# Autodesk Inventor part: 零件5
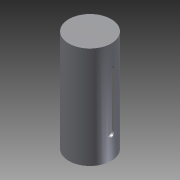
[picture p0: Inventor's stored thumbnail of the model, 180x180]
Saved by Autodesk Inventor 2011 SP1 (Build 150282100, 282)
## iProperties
Created: 2014-02
Part Number: 零件5
Document SubType Name: Modeling
Designer: yn
Density: 1 g/cm^3
Author: yn
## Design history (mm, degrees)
sketch "草图1"
  geometry: C1 r 12.5 at (0, 0); 1 further point
  constraints: 1 centre point, 1 coincident
  dimensions: "d0" = 25 diameter of C1
extrude "拉伸1" new body sketch "草图1" distance "d1" = 60; taper "d2" = 0 deg
node "工作平面1"
node "工作平面2"
sketch "草图3"
  geometry: L1 (-2, 14)-(-2, 46) reference; L2 (2, 14)-(2, 46) reference; A1 r 2 centre (0, 14) between (-2, 14) and (2, 14) reference; A2 r 2 centre (0, 46) between (2, 46) and (-2, 46) reference; 1 further point
extrude "拉伸2" cut sketch "草图3" distance "d9" = 2; taper "d10" = 0 deg
node "实体1"
other parameters: "d8" = 11
